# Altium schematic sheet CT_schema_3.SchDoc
size 288 x 169 mm
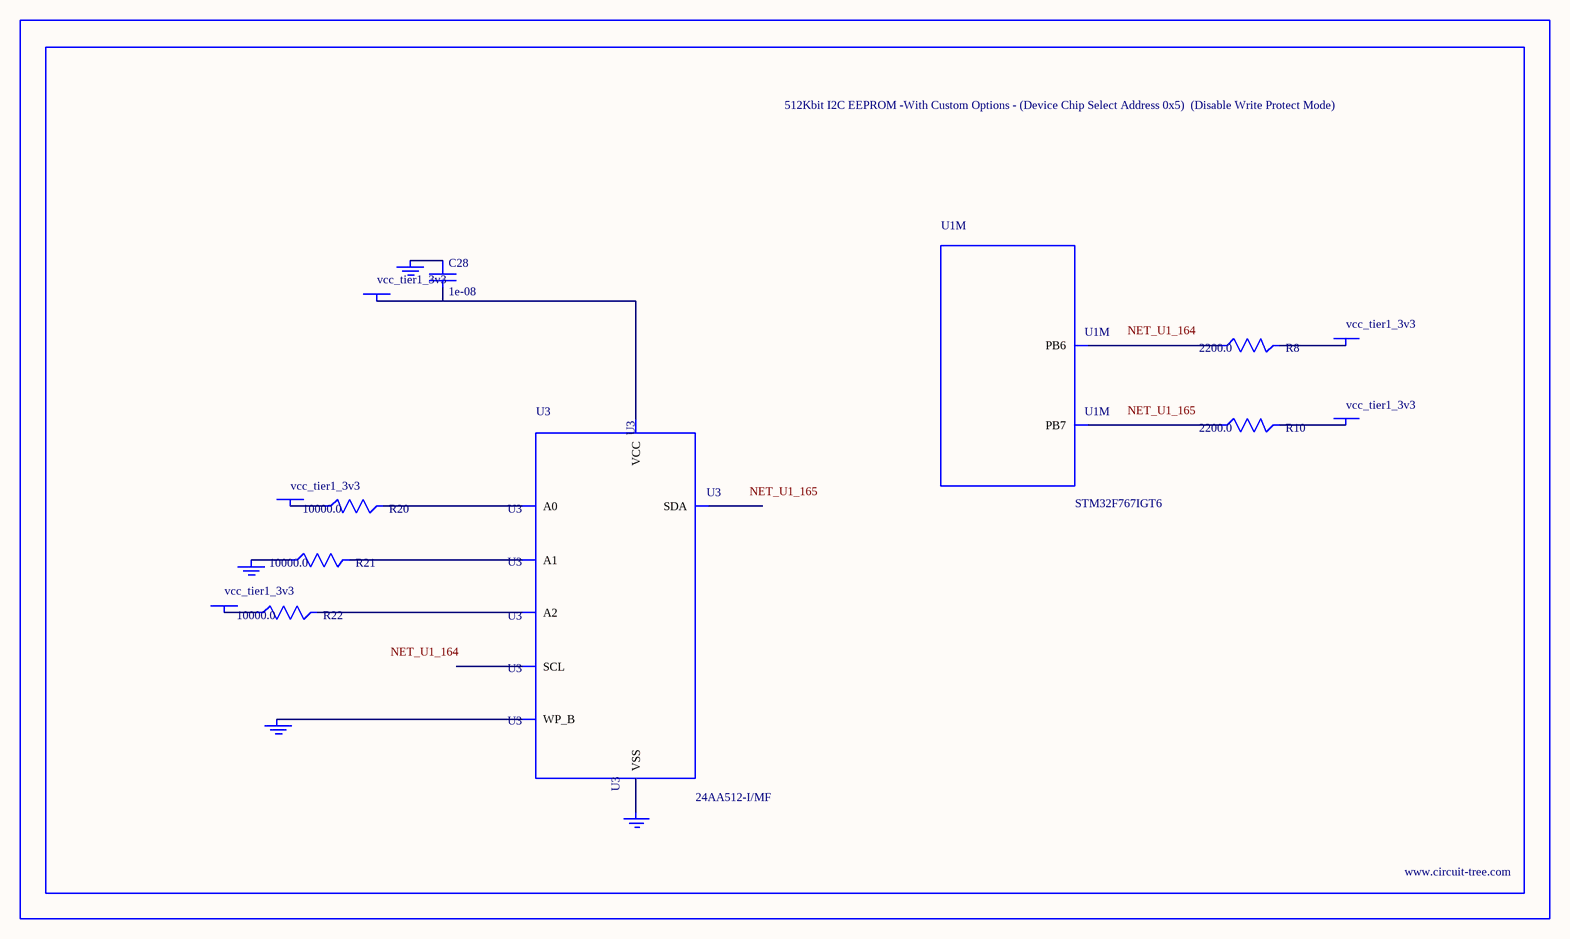
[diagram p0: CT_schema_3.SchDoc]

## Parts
BORDER2  (no value)
C28  1e-08  [C0402]
GND_INSTANCE_2_0  (no value)
GND_INSTANCE_2_1  (no value)
GND_INSTANCE_2_2  (no value)
GND_INSTANCE_2_3  (no value)
POWER_INSTANCE_2_0  vcc_tier1_3v3
POWER_INSTANCE_2_1  vcc_tier1_3v3
POWER_INSTANCE_2_2  vcc_tier1_3v3
POWER_INSTANCE_2_3  vcc_tier1_3v3
POWER_INSTANCE_2_4  vcc_tier1_3v3
R8  2200.0  [R0603]
R10  2200.0  [R0603]
R20  10000.0  [R0603]
R21  10000.0  [R0603]
R22  10000.0  [R0603]
U1  STM32F767IGT6  [LQFP176]  (part M of 13)
U3  24AA512-I/MF  [DFN8-S]

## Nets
NetC28_1: C28.1 GND_INSTANCE_2_2.0(GND)
NetC28_2: C28.2 POWER_INSTANCE_2_2.0(PWR) U3.8(VCC)
NetGND_INSTANCE_2_0_0: GND_INSTANCE_2_0.0(GND) R21.1
NetGND_INSTANCE_2_1_0: GND_INSTANCE_2_1.0(GND) U3.7(WP_B)
NetGND_INSTANCE_2_3_0: GND_INSTANCE_2_3.0(GND) U3.4(VSS)
NetPOWER_INSTANCE_2_0_0: POWER_INSTANCE_2_0.0(PWR) R20.1
NetPOWER_INSTANCE_2_1_0: POWER_INSTANCE_2_1.0(PWR) R22.1
NetPOWER_INSTANCE_2_3_0: POWER_INSTANCE_2_3.0(PWR) R8.2
NetPOWER_INSTANCE_2_4_0: POWER_INSTANCE_2_4.0(PWR) R10.2
NetR8_1: R8.1 U1.164(PB6)
NetR10_1: R10.1 U1.165(PB7)
NetR20_2: R20.2 U3.1(A0)
NetR21_2: R21.2 U3.2(A1)
NetR22_2: R22.2 U3.3(A2)

Not connected (* = marked no-connect by the designer): U3 5(SDA) 6(SCL)

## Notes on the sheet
- Labels drawn without touching a wire or pin: NET_U1_164, NET_U1_165

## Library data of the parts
BORDER2 = BORDER_PAGE2
C28 = C0402C103K3RAC
GND_INSTANCE_2_0-GND_INSTANCE_2_3 = GND
POWER_INSTANCE_2_0-POWER_INSTANCE_2_4 = PWR
R8 R10 = RC0603JR-072K2L
R20-R22 = RC0603JR-0710KL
